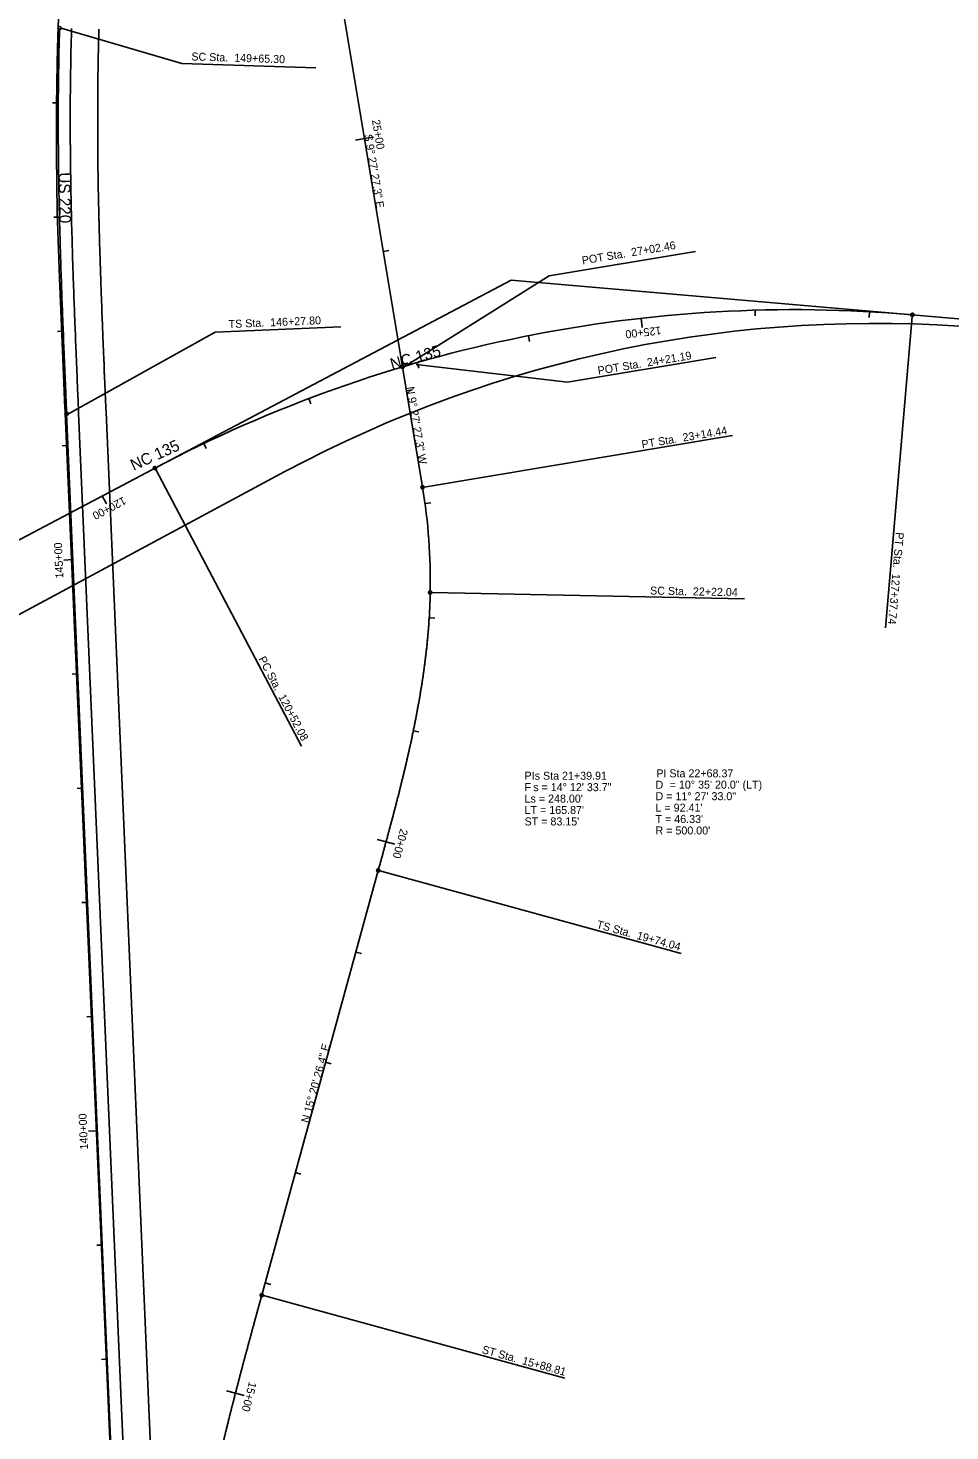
# Model space of a CAD drawing. Extents: x 1722038 to 1726172, y 967033 to 975427.
# Drawn here: x 1723895 to 1724702, y 971142 to 972370 of the extents above; entities that cross this region are included whole.
import ezdxf

# ---------------------------------------------------------------- set-up
doc = ezdxf.new("R2010")
doc.units = 0
for name, color, linetype in [('Prop Horizontal Alignment', 7, 'Continuous'), ('Prop Horizontal Alignment Curve and Spiral Data', 7, 'Continuous'), ('Prop Horizontal Alignment Direction Label', 7, 'Continuous'), ('Prop Horizontal Alignment Station Label', 7, 'Continuous'), ('Prop Horizontal Alignment Tick Label', 7, 'Continuous'), ('Prop Horizontal Alignment Tick Large', 7, 'Continuous'), ('Prop Horizontal Alignment Tick Small', 7, 'Continuous')]:
    doc.layers.add(name, color=color, linetype=linetype)

msp = doc.modelspace()

# ---------------------------------------------------------------- linework, layer by layer
at = {"layer": 'Prop Horizontal Alignment'}
for p, q in [((1724166.8, 972409.2), (1724222.8, 972073.2)), ((1723919.9, 972282.5), (1723919.9, 972288.6)), ((1723594.4, 971767.5), (1724317.8, 972149.1)), ((1723926.3, 972059.2), (1723922.5, 972151.2)), ((1724317.8, 972149.1), (1725070.7, 972084.2)), ((1724240.3, 971967.9), (1724222.8, 972073.2)), ((1724069.6, 968773.8), (1723927.1, 972039.3)), ((1724065.2, 968856.7), (1723928.8, 972032.2)), ((1724075.7, 968857.1), (1723939.3, 972032.7)), ((1724099.7, 968858.1), (1723963.3, 972033.7)), ((1723514.4, 971656.7), (1724119.9, 971981.6)), ((1724099.6, 971261.3), (1724201.5, 971632.8))]:
    msp.add_line(p, q, dxfattribs=at)
for centre, radius, start, end in [((1726238.9, 972290.2), 2318.8, 142.226, 178.7913), ((1726619.9, 972282.2), 2700, 178.7913, 179.863), ((1726919.9, 972275.3), 3000, 179.863, 182.3703), ((1724565.9, 970923.3), 1200, 85.0706, 117.8085), ((1724635.9, 971020), 1091.3, 85.0497, 118.2178), ((1732918.6, 972431.5), 9000, 182.37029, 182.49761), ((1723747.1, 971885.7), 500, 358.8687, 9.4576)]:
    msp.add_arc(centre, radius, start, end, dxfattribs=at)
for points in [[(1723928.8, 972032.2), (1723928.6, 972036.8), (1723928.4, 972041.4), (1723928.2, 972045.9), (1723928, 972050.5), (1723927.9, 972055), (1723927.7, 972059.6), (1723927.5, 972064.1), (1723927.3, 972068.7), (1723927.1, 972073.3), (1723926.9, 972077.8), (1723926.7, 972082.4), (1723926.5, 972086.9), (1723926.3, 972091.5), (1723926.1, 972096), (1723926, 972100.6), (1723925.8, 972105.2), (1723925.6, 972109.7), (1723925.4, 972114.3), (1723925.2, 972118.8), (1723925.1, 972123.4), (1723924.9, 972127.9), (1723924.7, 972132.5), (1723924.6, 972137.1), (1723924.4, 972141.6), (1723924.3, 972146.2), (1723924.1, 972150.7), (1723923.9, 972155.3), (1723923.8, 972159.8), (1723923.7, 972164.4), (1723923.5, 972169), (1723923.4, 972173.5), (1723923.2, 972178.1), (1723923.1, 972182.6), (1723923, 972187.2), (1723922.9, 972191.8), (1723922.7, 972196.3), (1723922.6, 972200.9), (1723922.5, 972205.4), (1723922.4, 972210), (1723922.3, 972214.6), (1723922.2, 972219.1), (1723922.1, 972223.7), (1723922, 972228.2), (1723922, 972232.8), (1723921.9, 972237.4), (1723921.8, 972241.9), (1723921.7, 972246.5), (1723921.7, 972251), (1723921.6, 972255.6), (1723921.6, 972260.2), (1723921.6, 972264.7), (1723921.5, 972269.3), (1723921.5, 972273.8), (1723921.5, 972278.4), (1723921.5, 972283), (1723921.5, 972287.5), (1723921.5, 972292.1), (1723921.5, 972296.6), (1723921.5, 972301.2), (1723921.5, 972305.8), (1723921.5, 972310.3), (1723921.6, 972314.9), (1723921.6, 972319.4), (1723921.7, 972324), (1723921.7, 972328.6), (1723921.8, 972333.1), (1723921.9, 972337.7), (1723921.9, 972342.3), (1723922, 972346.8), (1723922.1, 972351.4), (1723922.2, 972355.9), (1723922.4, 972360.5), (1723922.5, 972365), (1723922.6, 972369.6)], [(1723939.3, 972032.7), (1723939.1, 972037.3), (1723938.9, 972041.8), (1723938.7, 972046.4), (1723938.5, 972050.9), (1723938.3, 972055.5), (1723938.1, 972060), (1723938, 972064.6), (1723937.8, 972069.1), (1723937.6, 972073.7), (1723937.4, 972078.2), (1723937.2, 972082.8), (1723937, 972087.4), (1723936.8, 972091.9), (1723936.6, 972096.5), (1723936.5, 972101), (1723936.3, 972105.6), (1723936.1, 972110.1), (1723935.9, 972114.7), (1723935.7, 972119.2), (1723935.6, 972123.8), (1723935.4, 972128.3), (1723935.2, 972132.9), (1723935.1, 972137.4), (1723934.9, 972142), (1723934.7, 972146.5), (1723934.6, 972151.1), (1723934.4, 972155.6), (1723934.3, 972160.2), (1723934.1, 972164.7), (1723934, 972169.3), (1723933.9, 972173.8), (1723933.7, 972178.4), (1723933.6, 972182.9), (1723933.5, 972187.5), (1723933.3, 972192), (1723933.2, 972196.6), (1723933.1, 972201.1), (1723933, 972205.7), (1723932.9, 972210.2), (1723932.8, 972214.8), (1723932.7, 972219.3), (1723932.6, 972223.9), (1723932.5, 972228.4), (1723932.5, 972233), (1723932.4, 972237.5), (1723932.3, 972242.1), (1723932.2, 972246.6), (1723932.2, 972251.2), (1723932.1, 972255.7), (1723932.1, 972260.3), (1723932.1, 972264.8), (1723932, 972269.3), (1723932, 972273.9), (1723932, 972278.4), (1723932, 972283), (1723932, 972287.5), (1723932, 972292.1), (1723932, 972296.6), (1723932, 972301.2), (1723932, 972305.7), (1723932, 972310.3), (1723932.1, 972314.8), (1723932.1, 972319.3), (1723932.2, 972323.9), (1723932.2, 972328.4), (1723932.3, 972333), (1723932.4, 972337.5), (1723932.4, 972342), (1723932.5, 972346.6), (1723932.6, 972351.1), (1723932.7, 972355.7), (1723932.9, 972360.2), (1723933, 972364.7), (1723933.1, 972369.3)], [(1723963.3, 972033.7), (1723963.1, 972038.3), (1723962.9, 972042.8), (1723962.7, 972047.4), (1723962.5, 972051.9), (1723962.3, 972056.5), (1723962.1, 972061), (1723961.9, 972065.6), (1723961.7, 972070.1), (1723961.6, 972074.7), (1723961.4, 972079.2), (1723961.2, 972083.8), (1723961, 972088.3), (1723960.8, 972092.9), (1723960.6, 972097.4), (1723960.4, 972102), (1723960.3, 972106.5), (1723960.1, 972111.1), (1723959.9, 972115.6), (1723959.7, 972120.1), (1723959.6, 972124.7), (1723959.4, 972129.2), (1723959.2, 972133.8), (1723959.1, 972138.3), (1723958.9, 972142.8), (1723958.7, 972147.4), (1723958.6, 972151.9), (1723958.4, 972156.4), (1723958.3, 972161), (1723958.1, 972165.5), (1723958, 972170), (1723957.9, 972174.6), (1723957.7, 972179.1), (1723957.6, 972183.6), (1723957.5, 972188.1), (1723957.3, 972192.7), (1723957.2, 972197.2), (1723957.1, 972201.7), (1723957, 972206.2), (1723956.9, 972210.8), (1723956.8, 972215.3), (1723956.7, 972219.8), (1723956.6, 972224.3), (1723956.5, 972228.9), (1723956.5, 972233.4), (1723956.4, 972237.9), (1723956.3, 972242.4), (1723956.2, 972246.9), (1723956.2, 972251.5), (1723956.1, 972256), (1723956.1, 972260.5), (1723956.1, 972265), (1723956, 972269.5), (1723956, 972274), (1723956, 972278.5), (1723956, 972283), (1723956, 972287.6), (1723956, 972292.1), (1723956, 972296.6), (1723956, 972301.1), (1723956, 972305.6), (1723956, 972310.1), (1723956.1, 972314.6), (1723956.1, 972319.1), (1723956.2, 972323.6), (1723956.2, 972328.1), (1723956.3, 972332.6), (1723956.4, 972337.1), (1723956.4, 972341.6), (1723956.5, 972346.1), (1723956.6, 972350.6), (1723956.7, 972355.1), (1723956.8, 972359.6), (1723957, 972364.1), (1723957.1, 972368.6)], [(1724201.5, 971632.8), (1724202.4, 971636), (1724203.3, 971639.2), (1724204.2, 971642.5), (1724205.1, 971645.7), (1724205.9, 971648.9), (1724206.8, 971652.2), (1724207.7, 971655.4), (1724208.6, 971658.6), (1724209.5, 971661.9), (1724210.3, 971665.1), (1724211.2, 971668.3), (1724212.1, 971671.6), (1724212.9, 971674.8), (1724213.8, 971678), (1724214.7, 971681.3), (1724215.5, 971684.5), (1724216.4, 971687.8), (1724217.2, 971691), (1724218, 971694.3), (1724218.9, 971697.5), (1724219.7, 971700.7), (1724220.5, 971704), (1724221.3, 971707.2), (1724222.1, 971710.5), (1724222.9, 971713.8), (1724223.7, 971717), (1724224.5, 971720.3), (1724225.3, 971723.5), (1724226, 971726.8), (1724226.8, 971730.1), (1724227.5, 971733.3), (1724228.3, 971736.6), (1724229, 971739.9), (1724229.7, 971743.1), (1724230.5, 971746.4), (1724231.2, 971749.7), (1724231.8, 971753), (1724232.5, 971756.3), (1724233.2, 971759.5), (1724233.8, 971762.8), (1724234.5, 971766.1), (1724235.1, 971769.4), (1724235.7, 971772.7), (1724236.3, 971776), (1724236.9, 971779.3), (1724237.5, 971782.6), (1724238.1, 971785.9), (1724238.6, 971789.2), (1724239.2, 971792.5), (1724239.7, 971795.8), (1724240.2, 971799.1), (1724240.7, 971802.4), (1724241.2, 971805.8), (1724241.6, 971809.1), (1724242.1, 971812.4), (1724242.5, 971815.7), (1724242.9, 971819.1), (1724243.3, 971822.4), (1724243.7, 971825.7), (1724244.1, 971829), (1724244.4, 971832.4), (1724244.7, 971835.7), (1724245, 971839.1), (1724245.3, 971842.4), (1724245.6, 971845.7), (1724245.8, 971849.1), (1724246, 971852.4), (1724246.3, 971855.8), (1724246.4, 971859.1), (1724246.6, 971862.5), (1724246.7, 971865.8), (1724246.9, 971869.2), (1724247, 971872.5), (1724247, 971875.9)], [(1724099.6, 971261.3), (1724098.8, 971258.4), (1724098.1, 971255.6), (1724097.3, 971252.8), (1724096.5, 971250), (1724095.7, 971247.2), (1724095, 971244.4), (1724094.2, 971241.5), (1724093.4, 971238.7), (1724092.7, 971235.9), (1724091.9, 971233.1), (1724091.1, 971230.3), (1724090.4, 971227.5), (1724089.6, 971224.6), (1724088.8, 971221.8), (1724088.1, 971219), (1724087.3, 971216.2), (1724086.6, 971213.4), (1724085.8, 971210.6), (1724085, 971207.7), (1724084.3, 971204.9), (1724083.5, 971202.1), (1724082.8, 971199.3), (1724082, 971196.5), (1724081.3, 971193.6), (1724080.5, 971190.8), (1724079.8, 971188), (1724079.1, 971185.2), (1724078.3, 971182.3), (1724077.6, 971179.5), (1724076.9, 971176.7), (1724076.1, 971173.9), (1724075.4, 971171), (1724074.7, 971168.2), (1724074, 971165.4), (1724073.2, 971162.6), (1724072.5, 971159.7), (1724071.8, 971156.9), (1724071.1, 971154.1), (1724070.4, 971151.2), (1724069.7, 971148.4), (1724069, 971145.6), (1724068.3, 971142.7), (1724067.6, 971139.9), (1724066.9, 971137), (1724066.3, 971134.2), (1724065.6, 971131.4), (1724064.9, 971128.5), (1724064.2, 971125.7), (1724063.6, 971122.8), (1724062.9, 971120), (1724062.3, 971117.2), (1724061.6, 971114.3), (1724061, 971111.5), (1724060.3, 971108.6), (1724059.7, 971105.8), (1724059.1, 971102.9), (1724058.5, 971100.1), (1724057.8, 971097.2), (1724057.2, 971094.4), (1724056.6, 971091.5), (1724056, 971088.6), (1724055.4, 971085.8), (1724054.8, 971082.9), (1724054.2, 971080.1), (1724053.7, 971077.2), (1724053.1, 971074.3), (1724052.5, 971071.5), (1724052, 971068.6), (1724051.4, 971065.8), (1724050.9, 971062.9), (1724050.3, 971060), (1724049.8, 971057.1), (1724049.3, 971054.3), (1724048.8, 971051.4)]]:
    msp.add_spline(points, degree=3, dxfattribs=at)
at = {"layer": 'Prop Horizontal Alignment Station Label'}
for p, q in [((1723924.1, 972369.6), (1724029.5, 972338.5)), ((1724029.5, 972338.5), (1724147, 972334.9)), ((1724351, 972153), (1724479.2, 972174.3)), ((1724224.3, 972073.4), (1724351, 972153)), ((1724668.9, 972117.3), (1724645.4, 971844.9)), ((1723930.3, 972032.3), (1724058.7, 972103.5)), ((1724058.7, 972103.5), (1724168.9, 972108.3)), ((1724234.6, 972075.2), (1724367.3, 972059.8)), ((1724367.3, 972059.8), (1724497, 972081.4)), ((1724241.8, 971968.1), (1724511.6, 972013.1)), ((1724006.8, 971983.4), (1724134.4, 971741.4)), ((1724248.5, 971875.8), (1724522, 971870.4)), ((1724203, 971632.4), (1724466.7, 971560)), ((1724101.1, 971260.9), (1724364.8, 971188.5))]:
    msp.add_line(p, q, dxfattribs=at)
for centre in [(1723922.6, 972369.6), (1724669, 972118.8), (1724222.8, 972073.2), (1724222.8, 972073.2), (1723928.8, 972032.2), (1724006.1, 971984.7), (1724240.3, 971967.9), (1724247, 971875.9), (1724201.5, 971632.8), (1724099.6, 971261.3)]:
    msp.add_circle(centre, 1.5, dxfattribs=at)
at = {"layer": 'Prop Horizontal Alignment Tick Large'}
for p, q in [((1724189.5, 972272.9), (1724181.6, 972271.6)), ((1724189.5, 972272.9), (1724197.4, 972274.2)), ((1724431.7, 972115.7), (1724432.6, 972107.8)), ((1723960, 971960.4), (1723963.7, 971953.3)), ((1723934.3, 971904.6), (1723926.3, 971904.2)), ((1724208.4, 971657.8), (1724200.6, 971659.9)), ((1724208.4, 971657.8), (1724216.1, 971655.7)), ((1723955.8, 971405), (1723947.8, 971404.7)), ((1724076.5, 971175.5), (1724068.8, 971177.5)), ((1724076.5, 971175.5), (1724084.3, 971173.5))]:
    msp.add_line(p, q, dxfattribs=at)
at = {"layer": 'Prop Horizontal Alignment Tick Small'}
for p, q in [((1723921.5, 972304.3), (1723916.5, 972304.3)), ((1723922.5, 972204.3), (1723917.5, 972204.2)), ((1724206, 972174.2), (1724210.9, 972175.1)), ((1724531.4, 972122.8), (1724531.5, 972117.8)), ((1724631.4, 972121.5), (1724631.1, 972116.5)), ((1723925.8, 972104.4), (1723920.8, 972104.2)), ((1724332.9, 972100.4), (1724333.9, 972095.5)), ((1724222.4, 972075.6), (1724227.3, 972076.4)), ((1724235.7, 972077), (1724237.1, 972072.1)), ((1724226.3, 972052.3), (1724231.2, 972053.1)), ((1724140.8, 972045.5), (1724142.6, 972040.8)), ((1723930, 972004.5), (1723925, 972004.3)), ((1724048.9, 972006.2), (1724051, 972001.7)), ((1724242.5, 971953.6), (1724247.5, 971954.3)), ((1724246.1, 971853.8), (1724251.1, 971853.5)), ((1723938.6, 971804.7), (1723933.6, 971804.4)), ((1724232.2, 971754.9), (1724237.1, 971753.9)), ((1723942.9, 971704.7), (1723937.9, 971704.5)), ((1723947.2, 971604.8), (1723942.2, 971604.6)), ((1724181.9, 971561.4), (1724186.8, 971560)), ((1723951.5, 971504.9), (1723946.5, 971504.7)), ((1724155.5, 971464.9), (1724160.3, 971463.6)), ((1724129, 971368.5), (1724133.8, 971367.2)), ((1723960.1, 971305.1), (1723955.1, 971304.9)), ((1724102.6, 971272), (1724107.4, 971270.7)), ((1723964.4, 971205.2), (1723959.4, 971205))]:
    msp.add_line(p, q, dxfattribs=at)

# ---------------------------------------------------------------- texts
at = {"layer": 'Prop Horizontal Alignment Curve and Spiral Data'}
for s, p in [('PIs Sta 21+39.91', (1724329.6, 971712.1)), ('PI Sta 22+68.37', (1724444.9, 971714.2)), ('F', (1724329.6, 971702.1)), ('s = 14%%d 12\' 33.7"', (1724337.2, 971702.1)), ('D', (1724444.2, 971704.2)), ('= 10%%d 35\' 20.0" (LT)', (1724456.6, 971704.3)), ("Ls = 248.00'", (1724329.6, 971692.1)), ('D = 11%%d 27\' 33.0"', (1724444.2, 971694.2)), ("LT = 165.87'", (1724329.6, 971682.1)), ("T = 46.33'", (1724444.2, 971674.2)), ("L = 92.41'", (1724444.2, 971684.2)), ("ST = 83.15'", (1724329.6, 971672.1)), ("R = 500.00'", (1724444.2, 971664.2))]:
    msp.add_text(s, height=7, dxfattribs=at).set_placement(p)
at = {"layer": 'Prop Horizontal Alignment Direction Label'}
for s, rotation, p in [('S 9%%d 27\' 27.3" E', 279.4576, (1724189.2, 972276.2)), ('N 9%%d 27\' 27.3" W', 279.4576, (1724226, 972055.4)), ('N 15%%d 20\' 26.4" E', 74.6593, (1724140.6, 971411.4))]:
    msp.add_text(s, height=7, rotation=rotation, dxfattribs=at).set_placement(p)
at = {"layer": 'Prop Horizontal Alignment Station Label'}
for s, rotation, p in [('SC Sta.  149+65.30', 358.2412, (1724037.9, 972341.3)), ('POT Sta.  27+02.46', 9.4576, (1724380.4, 972162.8)), ('TS Sta.  146+27.80', 2.4596, (1724070.7, 972107.1)), ('POT Sta.  24+21.19', 9.4576, (1724394.2, 972066.4)), ('PT Sta.  23+14.44', 9.4576, (1724432.6, 972001.9)), ('PT Sta.  127+37.74', 265.0706, (1724654.6, 971928.8)), ('SC Sta.  22+22.04', 358.8687, (1724439.4, 971874.1)), ('PC Sta.  120+52.08', 297.8085, (1724096.4, 971817.8)), ('TS Sta.  19+74.04', 344.6593, (1724392.1, 971582.5)), ('ST Sta.  15+88.81', 344.6593, (1724291.8, 971210.6))]:
    msp.add_text(s, height=7, rotation=rotation, dxfattribs=at).set_placement(p)
at = {"layer": 'Prop Horizontal Alignment Tick Label'}
for s, height, rotation, p in [('25+00', 7, 279.4576, (1724196, 972289)), ('US 220', 10, 271.1904, (1723921.7, 972243.3)), ('125+00', 7, 186.4217, (1724448.8, 972108.6)), ('NC 135', 10, 15.971, (1724213.6, 972070.6)), ('NC 135', 10, 24.3724, (1723987.4, 971982.2)), ('120+00', 7, 207.8085, (1723978.5, 971960)), ('145+00', 7, 92.4596, (1723926, 971888.3)), ('20+00', 7, 254.815, (1724220.9, 971669.7)), ('140+00', 7, 92.4596, (1723947.5, 971388.8)), ('15+00', 7, 255.531, (1724088.5, 971185.9))]:
    msp.add_text(s, height=height, rotation=rotation, dxfattribs=at).set_placement(p)

doc.saveas('drawing.dxf')
